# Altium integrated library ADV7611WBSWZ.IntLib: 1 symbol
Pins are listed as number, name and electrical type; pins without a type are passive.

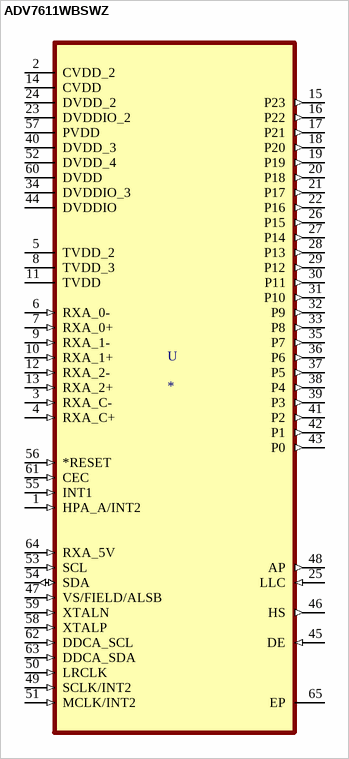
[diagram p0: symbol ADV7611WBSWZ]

## ADV7611WBSWZ
designator U
HDMI Receiver 1RX Automotive 64-Pin LQFP EP Tray; MF: Analog Devices; MP: ADV7611WBSWZ
footprint QFP50P1200X1200X160-65N
pins: 1 HPA_A/INT2 (in), 2 CVDD_2 (power), 3 RXA_C- (in), 4 RXA_C+ (in), 5 TVDD_2 (power), 6 RXA_0- (in), 7 RXA_0+ (in), 8 TVDD_3 (power), 9 RXA_1- (in), 10 RXA_1+ (in), 11 TVDD (power), 12 RXA_2- (in), 13 RXA_2+ (in), 14 CVDD (power), 15 P23 (out), 16 P22 (out), 17 P21 (out), 18 P20 (out), 19 P19 (out), 20 P18 (out), 21 P17 (out), 22 P16 (out), 23 DVDDIO_2 (power), 24 DVDD_2 (power), 25 LLC (in), 26 P15 (out), 27 P14 (out), 28 P13 (out), 29 P12 (out), 30 P11 (out), 31 P10 (out), 32 P9 (out), 33 P8 (out), 34 DVDDIO_3 (power), 35 P7 (out), 36 P6 (out), 37 P5 (out), 38 P4 (out), 39 P3 (out), 40 DVDD_3 (power), 41 P2 (out), 42 P1 (out), 43 P0 (out), 44 DVDDIO (power), 45 DE (in), 46 HS (out), 47 VS/FIELD/ALSB (in), 48 AP (out), 49 SCLK/INT2 (in), 50 LRCLK (in), 51 MCLK/INT2 (in), 52 DVDD_4 (power), 53 SCL (in), 54 SDA (io), 55 INT1 (in), 56 *RESET (in), 57 PVDD (power), 58 XTALP (in), 59 XTALN (in), 60 DVDD (power), 61 CEC (in), 62 DDCA_SCL (in), 63 DDCA_SDA (in), 64 RXA_5V (in), 65 EP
